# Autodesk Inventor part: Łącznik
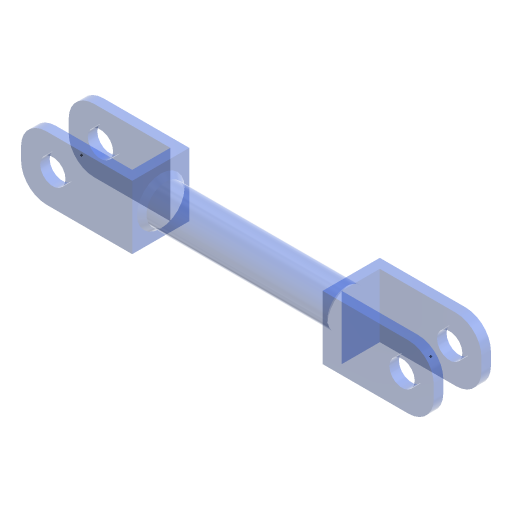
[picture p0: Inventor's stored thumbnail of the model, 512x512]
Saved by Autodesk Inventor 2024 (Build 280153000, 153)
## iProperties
Company: ATC
Shininess: 20.0
Angle Display Precision: 2
Document Length Units: 11269
Document Angle Units: 11279
Document Time Units: 11290
Document Mass Units: 11283
Document Length Units Precision: 3
Document Angle Units Precision: 2
Created: 2023-03
Part Number: Łącznik
Material: Stal węglowa
Document SubType Name: Modelowanie
Designer: Andrzej Jaskulski
Density: 7.87 g/cm^3
Stock Number: Łącznik
Mass: 124.227 g
Surface Area: 93.5667 cm^2
Volume: 15.7849 cm^3
Appearance: Stal
Checked By: A.J.
Engr Approved By: Andrzej Jaskulski
Mfg Approved By: Andrzej Jaskulski
Authority: A.J.
Density: 0.0
Volumn: 0.0
Area: 0.0
PropertySet Name: Model Information
Control State: 0
Master: False
Checked Out: False
Title: A.J.: Kurs R2024-MEP
Author: Andrzej Jaskulski
Revision Number: 1/24
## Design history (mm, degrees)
node "Początek"
  node "Płaszczyzna YZ"
  node "Płaszczyzna XZ"
  node "Płaszczyzna XY"
  node "Oś X"
  node "Oś Y"
  node "Oś Z"
node "Płaszczyzna konstrukcyjna1"
sketch "Szkic2"
  geometry: L1 (61.629, 12)-(29.629, 12); L2 (29.629, 0)-(61.629, 0); L3 (61.629, -3)-(26.629, -3); L4 (61.629, 12)-(61.629, 15); L5 (61.629, 15)-(26.629, 15); L6 (26.629, 15)-(26.629, -3); L7 (29.629, 12)-(29.629, 0); L8 (61.629, -3)-(61.629, 0)
  constraints: 16 end point, 4 parallel, 2 perpendicular
  dimensions: "d19" = 12 distance of L1.end L2.start; "d20" = 32 distance of L2.start L2.end; "d22" = 3 distance of L1.start L4.end; "d23" = 3 distance of L3.start L2.end (= d22); "d24" = 3 distance between parallel lines of L6 L7
extrude "Wyciągnięcie proste1" new body sketch "Szkic2" distance "d0" = 20; taper "d1" = 0 deg
sketch "Szkic3"
  geometry: L1 (0, 18)-(0, 0) reference; L2 (0, 18)-(-20, 18) reference; L3 (-20, 18)-(-20, 0) reference; C1 r 6 at (-10, 9)
  constraints: 1 centre point
  dimensions: "d4" = 12 diameter of C1; "d27" = 10 distance from line of C1.centre L3; "d28" = 9 distance from line of L2 C1.centre
extrude "Wyciągnięcie proste2" join sketch "Szkic3" distance "d5" = 60; taper "d6" = 0 deg
sketch "Szkic4"
  geometry: L1 (0, -20)-(35, -20) reference; L2 (35, 0)-(35, -20) reference; 1 further point
  dimensions: "d9" = 10 distance from line of L1 point (25, -10); "d10" = 10 distance from line of point (25, -10) L2
hole "Otwór1" sketch "Szkic4" diameter "d11" = 8; stored, may be unused: countersink angle "d15" = 82 deg, drill point angle "d17" = 118 deg; dims "d12" = 6, "d13" = 4, "d14" = 2, "d16" = 8
fillet "Zaokrąglenie1" dims "d18" = 8
chamfer "Faza1" distance "d25" = 1.5; stored, may be unused: second distance "d26" = 1.5, angle "d30" = 45 deg
node "Oś konstrukcyjna"
node "Oś konstrukcyjna3"
node "Płaszczyzna konstrukcyjna2"
mirror "Lustro1"
node "Oś konstrukcyjna4"
node "Przecięcie osi1"
node "Przecięcie osi2"
node "Bryła1"
node "Korpusy bryłowe"
node "Korpusy powierzchniowe"
node "Punkt środkowy"
other parameters: "sa_eq_min" = 2672.96, "sa_eq_max" = 154483, "sa_pmax_min" = -3917.54, "sa_pmax_max" = 186600, "sa_pmin_min" = -96857.1, "sa_pmin_max" = 24527.7, "sa_d_min" = 0.00004, "sa_d_max" = 0.00058, "d71" = 0, "d72" = 0, "d73" = 0, "d74" = 460.5, "d75" = 0, "d76" = -81274.8, "d77" = 0, "d78" = 0, "d79" = 0, "d80" = -546, "d81" = 0, "d82" = 5288, "d83" = 51452, "d84" = 0, "d85" = 292, "d86" = -49736, "d87" = 0, "d88" = -5135, "d90" = 18.4607
